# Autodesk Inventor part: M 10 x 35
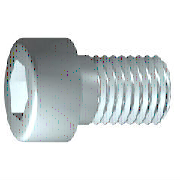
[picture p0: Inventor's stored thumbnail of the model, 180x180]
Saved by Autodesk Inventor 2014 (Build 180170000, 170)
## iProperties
IsCustomPart: 0
Created: 2009-02
Part Number: M 10 x 35
Material: 강, 연강
Description: 6각머리 태핑 나사
Document SubType Name: Modeling
Standard: KS B 1003
Designer: KYOUNG IL JANG
Standards Organization: KS
Language: ko-KR
Size Designation: M 10 x 35
Categories: <MemberInstance><Categories><Category DisplayName="조임쇠" InternalName="e4da775c-781d-43d5-af7c-5136215cf5a6" Mnemonic="FSTN"><Category DisplayName="볼트" InternalN
Density: 7.86 g/cm^3
Mass: 34.5961 g
Surface Area: 21.1658 cm^2
Volume: 4.40154 cm^3
Appearance: 강철
Author: KYOUNG IL JANG
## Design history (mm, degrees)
sketch "스케치1"
  geometry: L1 (-2.333, 0)-(35, 0); L2 (35, 0)-(35, 5); L3 (35, 5)-(3.75, 5); L4 (3.75, 5)-(2.83, 5); L5 (2.83, 5)-(0, 5); L6 (0, 5)-(0, 8); L7 (0, 8)-(-10, 8); L8 (-10, 8)-(-10, 4.619); L9 (-10, 4.619)-(-5, 4.619); L10 (-5, 4.619)-(-2.333, 0); L11 (-19, 0)-(44, 0) reference; L12 (0, -1.6)-(0, 9.6) reference; L13 (3.75, 5)-(0, 5)
  constraints: 22 end point, 6 parallel, 2 collinear, 2 perpendicular, 1 horizontal, 1 point on line
  dimensions: "d1" = 31.25 distance from line of L3.end L2 (= GEL); "d2" = 0.92028 distance of L4.end L3.end (computed from GAL); "d3" = 10 distance between parallel lines of L8 L6 (= KOH); "d4" = 5 distance of L8.end L9.end (= INTI); "d5" = 60 deg angle of L10 L1; "d6" = 10 diameter of L3 L1 (= GD); "d7" = 10 diameter of L5 L1 (= BDM); "d8" = 9.2376 diameter of L9 L1 (= 1.1547 x SW); "d9" = 16 diameter of L7 L1 (= KOD); "d26" = 35 distance between parallel lines of L12 L2 (= NLG)
revolve "본체" sketch "스케치1" stored, may be unused: angle "d10" = 90 deg
sketch "스케치2"
  geometry: L1 (0, -11.2)-(0, 11.2) reference; L2 (-11.2, 0)-(11.2, 0) reference; L3 (4.619, 0)-(2.309, -4); L4 (2.309, -4)-(-2.309, -4); L5 (-2.309, -4)-(-4.619, 0); L6 (-4.619, 0)-(-2.309, 4); L7 (-2.309, 4)-(2.309, 4); L8 (2.309, 4)-(4.619, 0); 2 further points
  constraints: 12 end point, 1 coincident, 1 horizontal alignment, 1 point on line, 12 other
extrude "슬롯" join sketch "스케치2" stored distance "d11" = 10; taper "d12" = 0 deg
workplane "Work Plane1"
fillet "Fillet2" dims "d30" = 0.1 (= R)
body "Solid1"
fillet "모깎기1" dims "d17" = 1 (= RR)
feature "스레드" dims "d13" = 31.25 (= GEL), "d14" = 0
chamfer "모따기1" distance "d15" = 0.92018 (= -0.5 x SPD + 0.5 x GD); stored, may be unused: second distance "d16" = 0.92018 (= GUL), angle "d27" = 45 deg
other parameters: "GD" = 10 (= NND) [user parameter; used in 2 equation terms], "NLG" = 35 [user parameter; used in 1 equation term], "GEL" = 31.25 [user parameter; used in 2 equation terms], "KOD" = 16 [user parameter; used in 1 equation term], "KOH" = 10 [user parameter; used in 1 equation term], "INTI" = 5 [user parameter; used in 1 equation term], "GAL" = 0.92018 (= 0.61345 x PTC) [user parameter; used in 1 equation term], "GUL" = 0.92018 (= 0.61345 x PTC) [user parameter; used in 1 equation term], "BDM" = 10 (= NND) [user parameter; used in 1 equation term], "SW" = 8 [user parameter; used in 2 equation terms], "RR" = 1 [user parameter; used in 1 equation term], "SPD" = 8.15965 (= NND - 1.2269 x PTC) [user parameter; used in 1 equation term], "d19" = 0, "d28" = 0, "d29" = 0, "R" = 0.1 [user parameter; used in 1 equation term], "PHH" = 0.4 [user parameter], "GD1" = 8.15965 (= THREADDIA - 1.2269 x PTC) [user parameter], "FAWI" = 45 deg [user parameter], "TPU" = 6.66667 (computed from PTC) [user parameter], "PTC" = 1.5 [user parameter; used in 5 equation terms], "TOA" = 30 deg [user parameter], "E0" = 9.24 (= 1.155 x SW) [user parameter]
